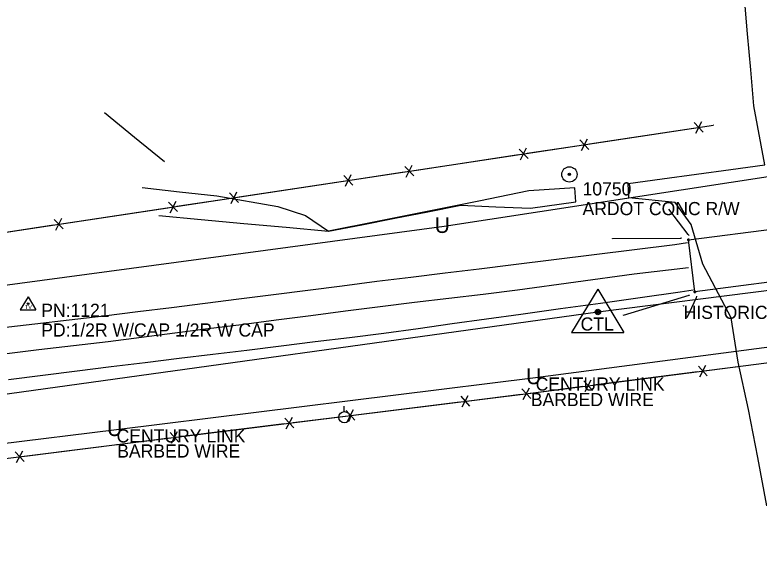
# Model space of a CAD drawing. Extents: x 1568433 to 1572450, y 731863 to 733450.
# Drawn here: x 1570266.2 to 1570549.4, y 732140.6 to 732343.4 of the extents above; entities that cross this region are included whole.
import ezdxf

# ---------------------------------------------------------------- set-up
doc = ezdxf.new("R2010")
doc.units = 0
for name, color, linetype in [('Default', 7, 'Continuous'), ('S_BASELINE', 7, 'Continuous'), ('S_BRIDGE', 7, 'Continuous'), ('S_DITCHLINE', 7, 'Continuous'), ('S_EDGE_PAVEMENT', 7, 'Continuous'), ('S_FENCE', 7, 'Continuous'), ('S_FENCE_ANNOT', 7, 'Continuous'), ('S_GUARDRAIL', 7, 'Continuous'), ('S_IRON_PIN', 7, 'Continuous'), ('S_IRON_PIN_ANNOT', 7, 'Continuous'), ('S_MSC_PT_SYM', 7, 'Continuous'), ('S_PAVEMENT_CROWN', 7, 'Continuous'), ('S_PRIMARY_CTL', 7, 'Continuous'), ('S_RDW_PT_SYM', 7, 'Continuous'), ('S_SECONDARY_CTL', 7, 'Continuous'), ('S_SECONDARY_CTL_ANNOT', 7, 'Continuous'), ('S_STR_PT_SYM', 7, 'Continuous'), ('S_STREAM', 7, 'Continuous'), ('S_SURVEY_TEXT_ANNOT', 7, 'Continuous'), ('S_UNDERGROUND_CABLE', 7, 'Continuous'), ('S_UNDERGROUND_CABLE_ANNOT', 7, 'Continuous'), ('S_UTILITY_POLE', 7, 'Continuous'), ('S_WALL', 7, 'Continuous')]:
    doc.layers.add(name, color=color, linetype=linetype)

msp = doc.modelspace()

# ---------------------------------------------------------------- linework, layer by layer
at = {"layer": 'Default'}
for points in [[(1570488.03, 732230.48), (1570488.03, 732230.53), (1570488.03, 732230.48), (1570487.98, 732230.48), (1570488.03, 732230.48), (1570488.03, 732230.43), (1570488.03, 732230.48), (1570488.08, 732230.48)], [(1570488.03, 732230.45), (1570488.03, 732230.5), (1570488.03, 732230.45), (1570487.98, 732230.45), (1570488.03, 732230.45), (1570488.03, 732230.4), (1570488.03, 732230.45), (1570488.08, 732230.45)], [(1570488.03, 732230.44), (1570488.03, 732230.49), (1570488.03, 732230.44), (1570487.98, 732230.44), (1570488.03, 732230.44), (1570488.03, 732230.39), (1570488.03, 732230.44), (1570488.08, 732230.44)], [(1570488.04, 732230.44), (1570488.04, 732230.49), (1570488.04, 732230.44), (1570487.99, 732230.44), (1570488.04, 732230.44), (1570488.04, 732230.39), (1570488.04, 732230.44), (1570488.09, 732230.44)], [(1570488.05, 732230.47), (1570488.05, 732230.52), (1570488.05, 732230.47), (1570488, 732230.47), (1570488.05, 732230.47), (1570488.05, 732230.42), (1570488.05, 732230.47), (1570488.1, 732230.47)], [(1570488.06, 732230.48), (1570488.06, 732230.53), (1570488.06, 732230.48), (1570488.01, 732230.48), (1570488.06, 732230.48), (1570488.06, 732230.43), (1570488.06, 732230.48), (1570488.11, 732230.48)], [(1570488.1, 732230.46), (1570488.1, 732230.51), (1570488.1, 732230.46), (1570488.05, 732230.46), (1570488.1, 732230.46), (1570488.1, 732230.41), (1570488.1, 732230.46), (1570488.15, 732230.46)], [(1570488.11, 732230.47), (1570488.11, 732230.52), (1570488.11, 732230.47), (1570488.06, 732230.47), (1570488.11, 732230.47), (1570488.11, 732230.42), (1570488.11, 732230.47), (1570488.16, 732230.47)]]:
    msp.add_lwpolyline(points, dxfattribs=at)
at = {"layer": 'S_BASELINE'}
for p, q in [((1570488.07, 732230.45), (1571317.07, 732336.49)), ((1569838.9, 732140.65), (1570488.07, 732230.45))]:
    msp.add_line(p, q, dxfattribs=at)
at = {"layer": 'S_BRIDGE'}
for p, q in [((1570522.49, 732257.91), (1570572.6, 732264.24)), ((1570524.95, 732238.13), (1570522.49, 732257.91)), ((1570574.94, 732244.65), (1570524.95, 732238.13))]:
    msp.add_line(p, q, dxfattribs=at)
at = {"layer": 'S_DITCHLINE'}
for points in [[(1570300.3, 732306.27), (1570311.73, 732296.95), (1570323.16, 732287.63)], [(1570314.63, 732277.74), (1570328.88, 732276.16), (1570343.13, 732274.59), (1570366.23, 732270.54), (1570376.79, 732267.18)], [(1570320.99, 732267.14), (1570337.15, 732265.64), (1570353.3, 732264.14), (1570369.45, 732262.63), (1570385.61, 732261.13), (1570398.19, 732263.61), (1570410.77, 732266.1), (1570423.36, 732268.58), (1570435.94, 732271.06), (1570449.19, 732270.48), (1570462.45, 732269.9), (1570479.62, 732272.29), (1570479.23, 732277.66), (1570461.78, 732276.45)], [(1570461.78, 732276.45), (1570442.74, 732272.62), (1570423.7, 732268.79), (1570404.65, 732264.96), (1570385.61, 732261.13)], [(1570376.79, 732267.18), (1570385.61, 732261.13)]]:
    msp.add_lwpolyline(points, dxfattribs=at)
at = {"layer": 'S_EDGE_PAVEMENT'}
for points in [[(1570260.59, 732224.37), (1570273.76, 732225.9), (1570286.93, 732227.43), (1570300.1, 732228.96), (1570312.95, 732230.58), (1570325.8, 732232.2), (1570338.65, 732233.82), (1570351.5, 732235.44), (1570364.6, 732237.11), (1570377.7, 732238.78), (1570390.79, 732240.44), (1570403.89, 732242.11), (1570416.91, 732243.69), (1570429.92, 732245.27), (1570442.94, 732246.86), (1570455.96, 732248.44), (1570471.31, 732250.37), (1570486.67, 732252.3), (1570502.02, 732254.23), (1570517.38, 732256.16), (1570522.16, 732256.86)], [(1570263.78, 732204.79), (1570276.82, 732206.44), (1570289.87, 732208.1), (1570302.91, 732209.75), (1570315.79, 732211.29), (1570328.68, 732212.83), (1570341.57, 732214.36), (1570354.45, 732215.9), (1570367.49, 732217.53), (1570380.53, 732219.16), (1570393.57, 732220.79), (1570406.61, 732222.42), (1570419.63, 732224.21), (1570432.66, 732226), (1570445.68, 732227.79), (1570458.7, 732229.58), (1570473.86, 732231.71), (1570489.01, 732233.84), (1570504.17, 732235.97), (1570519.32, 732238.1), (1570524.31, 732238.82)]]:
    msp.add_lwpolyline(points, dxfattribs=at)
at = {"layer": 'S_FENCE'}
for p, q in [((1570524.73, 732302.46), (1570528.18, 732298.84)), ((1570524.73, 732302.46), (1570528.18, 732298.84)), ((1570525.35, 732298.41), (1570527.57, 732302.89)), ((1570525.35, 732298.41), (1570527.57, 732302.89)), ((1570061.14, 732230.29), (1570532.01, 732301.49)), ((1570481.84, 732291.83), (1570484.06, 732296.31)), ((1570481.84, 732291.83), (1570484.06, 732296.31)), ((1570481.23, 732295.88), (1570484.68, 732292.26)), ((1570481.23, 732295.88), (1570484.68, 732292.26)), ((1570458.06, 732292.38), (1570461.51, 732288.75)), ((1570458.06, 732292.38), (1570461.51, 732288.75)), ((1570458.67, 732288.33), (1570460.89, 732292.8)), ((1570458.67, 732288.33), (1570460.89, 732292.8)), ((1570414.55, 732285.8), (1570418, 732282.18)), ((1570414.55, 732285.8), (1570418, 732282.18)), ((1570415.16, 732281.75), (1570417.39, 732286.23)), ((1570415.16, 732281.75), (1570417.39, 732286.23)), ((1570391.38, 732282.29), (1570394.83, 732278.67)), ((1570391.38, 732282.29), (1570394.83, 732278.67)), ((1570391.99, 732278.24), (1570394.22, 732282.72)), ((1570391.99, 732278.24), (1570394.22, 732282.72)), ((1570347.88, 732275.72), (1570351.32, 732272.1)), ((1570347.88, 732275.72), (1570351.32, 732272.1)), ((1570348.49, 732271.67), (1570350.71, 732276.15)), ((1570348.49, 732271.67), (1570350.71, 732276.15)), ((1570324.71, 732272.21), (1570328.15, 732268.59)), ((1570324.71, 732272.21), (1570328.15, 732268.59)), ((1570325.32, 732268.16), (1570327.54, 732272.64)), ((1570325.32, 732268.16), (1570327.54, 732272.64)), ((1570281.2, 732265.64), (1570284.65, 732262.01)), ((1570281.2, 732265.64), (1570284.65, 732262.01)), ((1570281.81, 732261.59), (1570284.04, 732266.06)), ((1570281.81, 732261.59), (1570284.04, 732266.06)), ((1570462.54, 732199.63), (1570593.81, 732216.49)), ((1570526.32, 732209.88), (1570529.69, 732206.19)), ((1570526.32, 732209.88), (1570529.69, 732206.19)), ((1570526.84, 732205.82), (1570529.17, 732210.25)), ((1570526.84, 732205.82), (1570529.17, 732210.25)), ((1570482.68, 732204.28), (1570486.05, 732200.58)), ((1570482.68, 732204.28), (1570486.05, 732200.58)), ((1570483.2, 732200.22), (1570485.52, 732204.65)), ((1570483.2, 732200.22), (1570485.52, 732204.65)), ((1570459.16, 732201.27), (1570462.51, 732197.56)), ((1570459.16, 732201.27), (1570462.51, 732197.56)), ((1570459.66, 732197.21), (1570462, 732201.63)), ((1570459.66, 732197.21), (1570462, 732201.63)), ((1570305.16, 732180.08), (1570462.54, 732199.63)), ((1570435.9, 732198.38), (1570439.25, 732194.67)), ((1570435.9, 732198.38), (1570439.25, 732194.67)), ((1570436.4, 732194.32), (1570438.75, 732198.74)), ((1570436.4, 732194.32), (1570438.75, 732198.74)), ((1570392.24, 732192.96), (1570395.59, 732189.25)), ((1570392.24, 732192.96), (1570395.59, 732189.25)), ((1570392.74, 732188.89), (1570395.08, 732193.31)), ((1570392.74, 732188.89), (1570395.08, 732193.31)), ((1570368.98, 732190.07), (1570372.33, 732186.36)), ((1570368.98, 732190.07), (1570372.33, 732186.36)), ((1570369.49, 732186), (1570371.83, 732190.42)), ((1570369.49, 732186), (1570371.83, 732190.42)), ((1570325.32, 732184.64), (1570328.67, 732180.93)), ((1570325.32, 732184.64), (1570328.67, 732180.93)), ((1570325.82, 732180.58), (1570328.16, 732185)), ((1570325.82, 732180.58), (1570328.16, 732185)), ((1570045.5, 732147.5), (1570305.16, 732180.08)), ((1570266.89, 732173.21), (1570269.22, 732177.63)), ((1570266.89, 732173.21), (1570269.22, 732177.63)), ((1570266.38, 732177.27), (1570269.73, 732173.57)), ((1570266.38, 732177.27), (1570269.73, 732173.57))]:
    msp.add_line(p, q, dxfattribs=at)
for points in [[(1570484.93, 732294.37), (1570524.48, 732300.35)], [(1570484.93, 732294.37), (1570524.48, 732300.35)], [(1570527.88, 732300.86), (1570532.01, 732301.49)], [(1570527.88, 732300.86), (1570532.01, 732301.49)], [(1570461.2, 732290.78), (1570480.97, 732293.77)], [(1570461.2, 732290.78), (1570480.97, 732293.77)], [(1570418.25, 732284.29), (1570457.8, 732290.27)], [(1570418.25, 732284.29), (1570457.8, 732290.27)], [(1570394.52, 732280.7), (1570414.3, 732283.69)], [(1570394.52, 732280.7), (1570414.3, 732283.69)], [(1570351.58, 732274.2), (1570391.13, 732280.18)], [(1570351.58, 732274.2), (1570391.13, 732280.18)], [(1570327.85, 732270.62), (1570347.62, 732273.61)], [(1570327.85, 732270.62), (1570347.62, 732273.61)], [(1570284.9, 732264.12), (1570324.45, 732270.1)], [(1570284.9, 732264.12), (1570324.45, 732270.1)], [(1570261.17, 732260.54), (1570280.95, 732263.53)], [(1570261.17, 732260.54), (1570280.95, 732263.53)], [(1570529.43, 732208.22), (1570549.26, 732210.77)], [(1570529.43, 732208.22), (1570549.26, 732210.77)], [(1570486.35, 732202.69), (1570526.02, 732207.78)], [(1570486.35, 732202.69), (1570526.02, 732207.78)], [(1570462.54, 732199.63), (1570482.38, 732202.18)], [(1570462.54, 732199.63), (1570482.38, 732202.18)], [(1570439, 732196.7), (1570458.85, 732199.17)], [(1570439, 732196.7), (1570458.85, 732199.17)], [(1570395.9, 732191.35), (1570435.59, 732196.28)], [(1570395.9, 732191.35), (1570435.59, 732196.28)], [(1570372.08, 732188.39), (1570391.93, 732190.86)], [(1570372.08, 732188.39), (1570391.93, 732190.86)], [(1570328.98, 732183.03), (1570368.67, 732187.97)], [(1570328.98, 732183.03), (1570368.67, 732187.97)], [(1570305.16, 732180.08), (1570325.01, 732182.54)], [(1570305.16, 732180.08), (1570325.01, 732182.54)], [(1570270.04, 732175.67), (1570305.16, 732180.08)], [(1570270.04, 732175.67), (1570305.16, 732180.08)]]:
    msp.add_lwpolyline(points, dxfattribs=at)
at = {"layer": 'S_GUARDRAIL'}
for p, q in [((1570493.63, 732258.4), (1570519.71, 732258.53)), ((1570497.83, 732229.27), (1570522.76, 732236.82))]:
    msp.add_line(p, q, dxfattribs=at)
at = {"layer": 'S_IRON_PIN'}
for radius in [2.91, 0.411, 0.262, 0.212, 0.145, 0.0822, 0.0581]:
    msp.add_circle((1570477.22, 732282.76), radius, dxfattribs=at)
at = {"layer": 'S_MSC_PT_SYM'}
for points in [[(1570532.01, 732301.49), (1570532.01, 732301.54), (1570532.01, 732301.49), (1570531.96, 732301.49), (1570532.01, 732301.49), (1570532.01, 732301.44), (1570532.01, 732301.49), (1570532.06, 732301.49)], [(1570520.69, 732232.8), (1570520.69, 732232.85), (1570520.69, 732232.8), (1570520.64, 732232.8), (1570520.69, 732232.8), (1570520.69, 732232.75), (1570520.69, 732232.8), (1570520.74, 732232.8)], [(1570462.54, 732199.63), (1570462.54, 732199.68), (1570462.54, 732199.63), (1570462.49, 732199.63), (1570462.54, 732199.63), (1570462.54, 732199.58), (1570462.54, 732199.63), (1570462.59, 732199.63)], [(1570305.16, 732180.08), (1570305.16, 732180.13), (1570305.16, 732180.08), (1570305.11, 732180.08), (1570305.16, 732180.08), (1570305.16, 732180.03), (1570305.16, 732180.08), (1570305.21, 732180.08)]]:
    msp.add_lwpolyline(points, dxfattribs=at)
at = {"layer": 'S_PAVEMENT_CROWN'}
msp.add_lwpolyline([(1570262.2, 732214.54), (1570275.38, 732216.12), (1570288.55, 732217.69), (1570301.73, 732219.27), (1570314.4, 732220.89), (1570327.07, 732222.5), (1570339.74, 732224.12), (1570352.41, 732225.73), (1570365.6, 732227.43), (1570378.79, 732229.13), (1570391.98, 732230.83), (1570405.17, 732232.53), (1570418.25, 732234.11), (1570431.33, 732235.68), (1570444.41, 732237.26), (1570457.49, 732238.83), (1570479.67, 732241.9), (1570501.86, 732244.97), (1570522.6, 732247.41)], dxfattribs=at)
at = {"layer": 'S_PRIMARY_CTL'}
for p, q in [((1570488.07, 732239.15), (1570478.03, 732222.64)), ((1570488.07, 732239.15), (1570478.03, 732222.64)), ((1570488.07, 732239.15), (1570497.89, 732222.64)), ((1570488.07, 732239.15), (1570497.89, 732222.64)), ((1570478.03, 732222.64), (1570497.89, 732222.64)), ((1570478.03, 732222.64), (1570497.89, 732222.64))]:
    msp.add_line(p, q, dxfattribs=at)
for radius in [1.04, 1.04, 0.609, 0.609, 0.344, 0.344]:
    msp.add_circle((1570488.07, 732230.45), radius, dxfattribs=at)
at = {"layer": 'S_RDW_PT_SYM'}
for points in [[(1570493.63, 732258.4), (1570493.63, 732258.45), (1570493.63, 732258.4), (1570493.58, 732258.4), (1570493.63, 732258.4), (1570493.63, 732258.35), (1570493.63, 732258.4), (1570493.68, 732258.4)], [(1570519.71, 732258.53), (1570519.71, 732258.58), (1570519.71, 732258.53), (1570519.66, 732258.53), (1570519.71, 732258.53), (1570519.71, 732258.48), (1570519.71, 732258.53), (1570519.76, 732258.53)], [(1570522.76, 732236.82), (1570522.76, 732236.87), (1570522.76, 732236.82), (1570522.71, 732236.82), (1570522.76, 732236.82), (1570522.76, 732236.77), (1570522.76, 732236.82), (1570522.81, 732236.82)], [(1570497.83, 732229.27), (1570497.83, 732229.32), (1570497.83, 732229.27), (1570497.78, 732229.27), (1570497.83, 732229.27), (1570497.83, 732229.22), (1570497.83, 732229.27), (1570497.88, 732229.27)]]:
    msp.add_lwpolyline(points, dxfattribs=at)
at = {"layer": 'S_SECONDARY_CTL'}
for p, q in [((1570271.25, 732236.2), (1570268.24, 732231.25)), ((1570271.25, 732236.2), (1570274.2, 732231.25)), ((1570268.24, 732231.25), (1570274.2, 732231.25))]:
    msp.add_line(p, q, dxfattribs=at)
for radius in [0.311, 0.183, 0.103]:
    msp.add_circle((1570271.25, 732233.59), radius, dxfattribs=at)
at = {"layer": 'S_STR_PT_SYM'}
for points in [[(1570522.49, 732257.91), (1570522.49, 732258.41), (1570522.49, 732257.91), (1570521.99, 732257.91), (1570522.49, 732257.91), (1570522.49, 732257.41), (1570522.49, 732257.91), (1570522.99, 732257.91)], [(1570524.95, 732238.13), (1570524.95, 732238.63), (1570524.95, 732238.13), (1570524.45, 732238.13), (1570524.95, 732238.13), (1570524.95, 732237.63), (1570524.95, 732238.13), (1570525.45, 732238.13)]]:
    msp.add_lwpolyline(points, dxfattribs=at)
at = {"layer": 'S_STREAM'}
for points in [[(1570551.64, 732286.45), (1570547.43, 732308.84), (1570546.23, 732322.53), (1570545.02, 732336.22), (1570543.82, 732349.9)], [(1570552.41, 732156.78), (1570548.9, 732175.08), (1570545.39, 732193.38), (1570541.5, 732211.34), (1570538.83, 732228.18), (1570527.96, 732248.57), (1570523.52, 732263.68), (1570517.44, 732272.08), (1570499.79, 732273.82), (1570499.55, 732279.33), (1570512.57, 732281.11), (1570525.6, 732282.89), (1570538.62, 732284.67), (1570551.64, 732286.45)]]:
    msp.add_lwpolyline(points, dxfattribs=at)
at = {"layer": 'S_UNDERGROUND_CABLE'}
for p, q in [((1570429.57, 732263.04), (1570580.49, 732286.26)), ((1570079.83, 732216.06), (1570429.57, 732263.04)), ((1570464.38, 732205.53), (1570619.91, 732225.92)), ((1570304.92, 732185.81), (1570464.38, 732205.53)), ((1570176.6, 732170.01), (1570304.92, 732185.81))]:
    msp.add_line(p, q, dxfattribs=at)
at = {"layer": 'S_UTILITY_POLE'}
msp.add_line((1570391.49, 732192.55), (1570391.49, 732194.66), dxfattribs=at)
msp.add_circle((1570391.61, 732190.41), 2.13, dxfattribs=at)
at = {"layer": 'S_WALL'}
for points in [[(1570522.83, 732259.52), (1570522.38, 732259.87), (1570515.09, 732269.55)], [(1570525.62, 732236.48), (1570525.5, 732235.77), (1570521.96, 732228.24)]]:
    msp.add_lwpolyline(points, dxfattribs=at)

# ---------------------------------------------------------------- texts
at = {"layer": 'Default'}
for p in [(1570425.94, 732260.49), (1570460.75, 732202.98), (1570301.29, 732183.27)]:
    msp.add_text('U', height=6, dxfattribs=at).set_placement(p)
at = {"layer": 'S_FENCE_ANNOT'}
for p in [(1570462.54, 732194.63), (1570305.16, 732175.08)]:
    msp.add_text('BARBED WIRE', height=5, dxfattribs=at).set_placement(p)
at = {"layer": 'S_IRON_PIN_ANNOT'}
for s, p in [('10750', (1570482.22, 732274.76)), ('ARDOT CONC R/W', (1570482.22, 732267.26))]:
    msp.add_text(s, height=5, dxfattribs=at).set_placement(p)
at = {"layer": 'S_PRIMARY_CTL'}
msp.add_text('CTL', height=5, rotation=360, dxfattribs=at).set_placement((1570481.48, 732223.37))
msp.add_text('CTL', height=5, dxfattribs=at).set_placement((1570481.48, 732223.37))
at = {"layer": 'S_SECONDARY_CTL'}
msp.add_text('TV', height=1.5, dxfattribs=at).set_placement((1570270.05, 732231.58))
at = {"layer": 'S_SECONDARY_CTL_ANNOT'}
for s, p in [('PN:1121', (1570276.25, 732228.59)), ('PD:1/2R W/CAP 1/2R W CAP', (1570276.25, 732221.09))]:
    msp.add_text(s, height=5, dxfattribs=at).set_placement(p)
at = {"layer": 'S_SURVEY_TEXT_ANNOT'}
msp.add_text('HISTORIC HIGH WATER DATE 2017 P', height=5, dxfattribs=at).set_placement((1570520.69, 732227.8))
at = {"layer": 'S_UNDERGROUND_CABLE_ANNOT'}
for p in [(1570464.38, 732200.53), (1570304.92, 732180.81)]:
    msp.add_text('CENTURY LINK', height=5, dxfattribs=at).set_placement(p)

doc.saveas('drawing.dxf')
